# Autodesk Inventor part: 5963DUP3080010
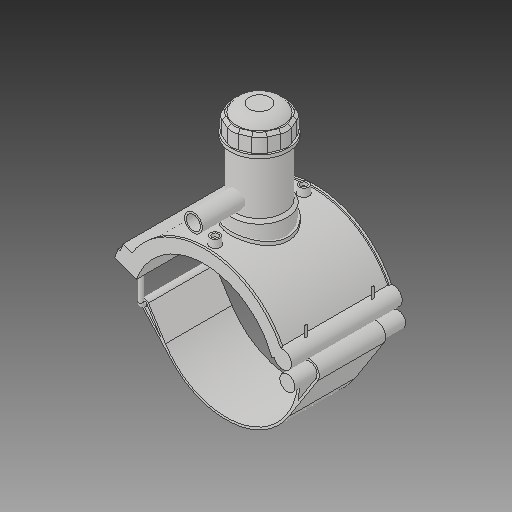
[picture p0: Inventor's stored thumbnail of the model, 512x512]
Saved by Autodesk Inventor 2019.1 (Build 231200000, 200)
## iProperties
Created: 2017-07
Part Number: 5963DUP3080010
Material: Generic
Description: PLASSON TAPPING SADDLE 8''DIPS x 1''CTS
Document SubType Name: Modeling
Designer: KIM
Density: 1 g/cm^3
Appearance: Default
Author: KIM
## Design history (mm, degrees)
derived "5963DBP_5963BUP.ipt"
feature "Solid1::5963DBP_5963BUP.ipt"
feature "Solid2::5963DBP_5963BUP.ipt"
feature "Solid3::5963DBP_5963BUP.ipt"
tag "TaggingFeature1"
body "Solid1"
body "Solid2"
body "Solid3"
other parameters: "d0" = 228.9, "d2" = 269.748, "d3" = 57.225, "d4" = 176.022, "d5" = 0, "d6" = 0.1, "d8" = 0, "d19" = 6, "d20" = 6, "d21" = 105.6132, "d23" = 0, "d24" = 52.8066, "d26" = 0, "d27" = 3, "d28" = 3, "d29" = 3, "d30" = 76.3, "d31" = 6, "d32" = 0, "d33" = 0, "d34" = 0.6, "d40" = 138.07248, "d41" = 91.56, "d43" = 0, "d45" = 0, "d47" = 238.3752, "d70" = 15, "d72" = 0, "d73" = 6, "d75" = 5, "d76" = 0, "d77" = 11.445, "d78" = 144.45, "d79" = 15, "d80" = 70.4088, "d82" = 5 deg, "d84" = 4, "d85" = 14, "d86" = 0, "d87" = 3, "d88" = 0, "d89" = 1, "d90" = 1, "d91" = 140.8176, "d92" = 0, "d93" = 0.5, "d94" = 120.47368, "d96" = 270.83448, "d97" = 3.52044, "d98" = 0, "d120" = 140 deg, "d121" = 24.228, "d122" = 20 deg, "d123" = 531.048, "d124" = 159.3144, "d126" = 0, "d143" = 235.767, "d145" = 28.17231, "d149" = 3.4335, "d150" = 30.98954, "d153" = 176.022, "d154" = 0, "d156" = 132.762, "d157" = 160 deg, "d159" = 7.3248, "d161" = 3.4335, "d162" = 105.6132, "d163" = 0, "d164" = 114.45, "d167" = 22.89, "d168" = 129.5239, "d170" = 3.4335, "d172" = 0, "d173" = 1, "d175" = 114.45, "d176" = 20 deg, "d177" = 16.023, "d178" = 36.624, "d180" = 0, "d183" = 14.6496, "d184" = 12.8184, "d185" = 57.20715, "d186" = 57.20715, "d187" = 132.762, "d188" = 10.9872, "d189" = 16.023, "d190" = 0, "d191" = 199.143, "d193" = 7.3248, "d194" = 6.16077, "d195" = 90 deg, "d197" = 0, "d199" = 0, "d200" = 18.312, "d202" = 0, "d203" = 177.038, "d204" = 86.982, "d205" = 64.092, "d206" = 77.826, "d207" = 132.7785, "d208" = 138.08964, "d209" = 164.64534, "d210" = 78.7416, "d211" = 91.56, "d212" = 73.248, "d213" = 45.7191, "d216" = 0, "d217" = 22.89, "d218" = 22.89, "d219" = 4.578, "d222" = 228.9, "d224" = 0, "d225" = 65.024, "d226" = 28.45, "d227" = 22.76, "d228" = 104.902, "d230" = 4.578, "d_" = 228.9, "B_" = 179.832, "L_" = 176.022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
